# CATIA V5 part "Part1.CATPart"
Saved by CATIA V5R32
Part number: Part1
Bounding box of the stored display mesh (mm): x -100 to 100, y -54.891 to 54.891, z 0 to 20
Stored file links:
  D:\PROJECTS\Project 2022\CATIA V5 6R 2022\Resources\Part Files\c16_catia_v5_6r2022_prt\Roll Curve Joint-(Fig16-43)\Part1.CATPart
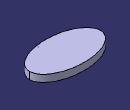
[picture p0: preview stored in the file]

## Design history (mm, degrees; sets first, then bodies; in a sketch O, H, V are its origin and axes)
Body1 (main body)
  Sketch1 on xy-plane, origin (0, 0, 0), H (1, 0, 0), V (0, 1, 0)
    point P1 (0, 0)
    ellipse A1 centre (0, 0) semi-axes 100, 55 rotation 0
    "Radius" A1 = 100
    "Radius" A1 = 55
    angle V A1 = 90
    coincidence: P1 H, P1 V
  Pad1: profile Sketch1, direction (0, 0, 1), length 20
  Point1: type OnCurve, Support edge [face of Pad1 from Sketch1.A1 | end face of Pad1], RefPoint {extremum Reference edge [face of Pad1 from Sketch1.A1 | end face of Pad1], Direction (1, 2, 3)}, Length 344.171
